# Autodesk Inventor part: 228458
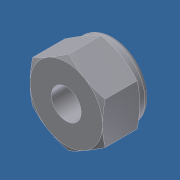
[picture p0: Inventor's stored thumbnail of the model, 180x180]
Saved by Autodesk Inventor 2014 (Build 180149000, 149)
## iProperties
Shininess: 20.0
Length Units: 11272
Angle Units: 11279
Time Units: 11290
Mass Units: 11286
Length Display Precision: 3
Angle Display Precision: 2
Company: Autodesk, Inc.
Created: 2001-10
Part Number: 228458
Material: Stainless Steel, 440C
Description: Nut, Esna; 5/8~11 (SS)
Document SubType Name: Modeling
Designer: Autodesk, Inc.
Density: 7.75 g/cm^3
Mass: 46.399 g
Surface Area: 29.4927 cm^2
Volume: 5.98697 cm^3
Appearance: Steel
Density: 8.94
Volumn: 1.3062604850048036
Area: 10.612586411503024
PropertySet Name: Model Information
Control State: 0
Master: False
Checked Out: True
Last Check In By: JT
Last Check In Date: 2003-06-20
MODEL - 1: ---
MODEL - 2: ---
RAW MATERIAL: --------
SCALE:: 1=??
SIZE: 00 x 00 x 00
SUB-ASSY - 1: ------
SUB-ASSY - 1 - QUA: 1
SUB-ASSY - 2: ------
SUB-ASSY - 2 - QUA: 1
SYM. TO:: N/A
TEMPLATE CREATION: -- / __-__-__
Author: Autodesk, Inc.
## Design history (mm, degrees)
derived "Lock-nut.ipt"
body "Solid1"
tag "TaggingFeature2"
feature "Solid1::Lock-nut.ipt" dims "ScaleForDerivedMember" = 10
